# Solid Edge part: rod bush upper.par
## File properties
Author: Robert a Rhodes jr
Template: Normal.par
Last saved by: CADCIM
Revision: 6
Application: Solid Edge
Accuracy: 0.99
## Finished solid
Body 1: solid body, 4 faces, 4 edges, 0 vertices.
  Faces by surface: cylinder 2, plane 2
  Edges by curve: circle 4
Bounding box of the edges (mm): 24.000 x 24.000 x 42.000, from (-12, -12, -42) to (12, 12, 0).
Cylindrical faces by radius (mm): R11 x1, R12 x1
Planar faces by outward normal: +z 1, -z 1
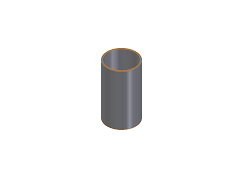
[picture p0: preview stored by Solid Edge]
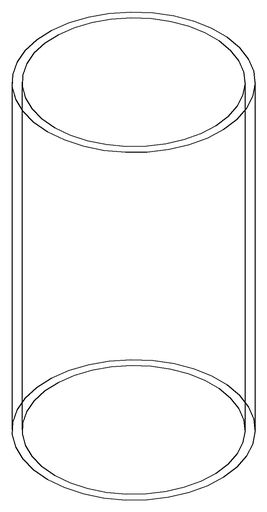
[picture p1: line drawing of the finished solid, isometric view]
